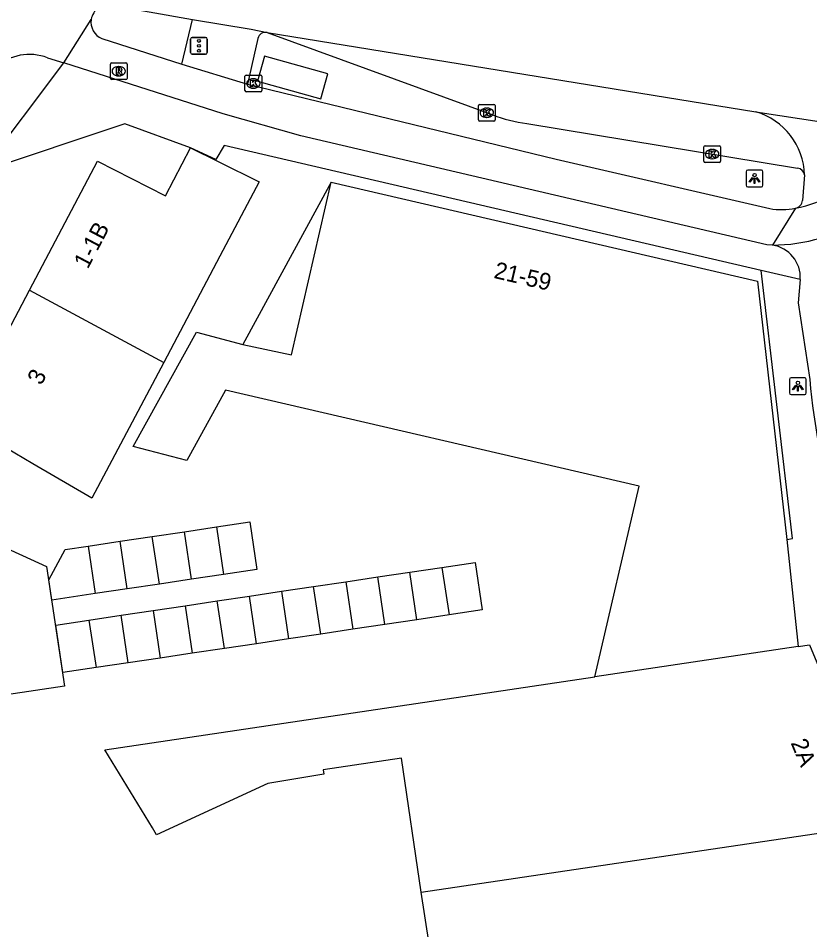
# Model space of a CAD drawing. Extents: x 161771 to 163125, y 382479 to 383177.
# Drawn here: x 161847.7 to 161894.8, y 383087.1 to 383141.3 of the extents above; entities that cross this region are included whole.
import ezdxf

# ---------------------------------------------------------------- set-up
doc = ezdxf.new("R2010")
doc.units = 0
for name, color, linetype in [('IMGEO_Fietspad_gesloten', 7, 'Continuous'), ('IMGEO_Kolk', 7, 'Continuous'), ('IMGEO_Lichtpunt', 7, 'Continuous'), ('IMGEO_Pand', 7, 'Continuous'), ('IMGEO_Pand_nummerreeks', 7, 'Continuous'), ('IMGEO_Pand_overbouw', 7, 'Continuous'), ('IMGEO_Rijbaan_lokaal_gesloten', 7, 'Continuous'), ('IMGEO_Rijbaan_lokaal_open', 7, 'Continuous'), ('IMGEO_Rioolput', 7, 'Continuous'), ('IMGEO_Verkeersregelinstallatiepaal', 7, 'Continuous'), ('IMGEO_Voetpad_gesloten', 7, 'Continuous'), ('IMGEO_Voetpad_open', 7, 'Continuous')]:
    doc.layers.add(name, color=color, linetype=linetype)

msp = doc.modelspace()

# ---------------------------------------------------------------- linework, layer by layer
at = {"layer": 'IMGEO_Fietspad_gesloten'}
for points in [[(161852.692, 383140.086), (161857.449, 383138.559)], [(161892.571, 383127.801), (161892.245, 383127.819), (161864.526, 383134.302), (161859.902, 383135.61), (161850.423, 383138.63)], [(161857.449, 383138.559), (161861.339, 383137.377)], [(161861.339, 383137.377), (161879.714, 383132.903), (161892.418, 383129.967)]]:
    msp.add_lwpolyline(points, dxfattribs=at)
for centre, radius, start, end in [((161853.077, 383141.052), 1.04, 170.4087, 248.2543), ((161893.117, 383134.045), 4.137, 260.2727, 281.4599)]:
    msp.add_arc(centre, radius, start, end, dxfattribs=at)
at = {"layer": 'IMGEO_Kolk'}
for p, q in [((161861.198, 383136.985), (161861.198, 383137.837)), ((161861.273, 383137.911), (161862.125, 383137.911)), ((161861.686, 383137.691), (161861.711, 383137.691)), ((161862.199, 383137.837), (161862.199, 383136.985)), ((161862.125, 383136.911), (161861.273, 383136.911)), ((161861.709, 383137.131), (161861.684, 383137.131)), ((161875.083, 383135.244), (161875.083, 383136.096)), ((161875.158, 383136.17), (161876.01, 383136.17)), ((161875.571, 383135.95), (161875.596, 383135.95)), ((161876.084, 383136.096), (161876.084, 383135.244)), ((161875.594, 383135.39), (161875.569, 383135.39)), ((161876.01, 383135.17), (161875.158, 383135.17)), ((161888.49, 383132.785), (161888.49, 383133.637)), ((161888.565, 383133.711), (161889.417, 383133.711)), ((161889.491, 383133.637), (161889.491, 383132.785)), ((161888.978, 383133.491), (161889.003, 383133.491)), ((161889.417, 383132.711), (161888.565, 383132.711)), ((161889.001, 383132.931), (161888.976, 383132.931))]:
    msp.add_line(p, q, dxfattribs=at)
for points in [[(161861.198, 383136.985), (161861.198, 383137.837)], [(161861.273, 383137.911), (161862.125, 383137.911)], [(161861.519, 383137.611), (161861.642, 383137.611), (161861.642, 383137.46), (161861.772, 383137.611), (161861.936, 383137.611), (161861.79, 383137.46), (161861.943, 383137.211), (161861.791, 383137.211), (161861.706, 383137.375), (161861.642, 383137.308), (161861.642, 383137.211), (161861.519, 383137.211), (161861.519, 383137.611)], [(161862.199, 383137.837), (161862.199, 383136.985)], [(161862.125, 383136.911), (161861.273, 383136.911)], [(161875.083, 383135.244), (161875.083, 383136.096)], [(161875.158, 383136.17), (161876.01, 383136.17)], [(161875.404, 383135.87), (161875.527, 383135.87), (161875.527, 383135.719), (161875.657, 383135.87), (161875.821, 383135.87), (161875.675, 383135.719), (161875.828, 383135.47), (161875.676, 383135.47), (161875.591, 383135.634), (161875.527, 383135.567), (161875.527, 383135.47), (161875.404, 383135.47), (161875.404, 383135.87)], [(161876.084, 383136.096), (161876.084, 383135.244)], [(161876.01, 383135.17), (161875.158, 383135.17)], [(161888.49, 383132.785), (161888.49, 383133.637)], [(161888.565, 383133.711), (161889.417, 383133.711)], [(161889.491, 383133.637), (161889.491, 383132.785)], [(161888.811, 383133.411), (161888.934, 383133.411), (161888.934, 383133.26), (161889.064, 383133.411), (161889.228, 383133.411), (161889.082, 383133.26), (161889.235, 383133.011), (161889.083, 383133.011), (161888.998, 383133.175), (161888.934, 383133.108), (161888.934, 383133.011), (161888.811, 383133.011), (161888.811, 383133.411)], [(161889.417, 383132.711), (161888.565, 383132.711)]]:
    msp.add_lwpolyline(points, dxfattribs=at)
for centre, start, end in [((161861.275, 383137.835), 91.552, 178.448), ((161861.275, 383137.835), 91.552, 178.448), ((161862.123, 383137.835), 1.552, 88.448), ((161862.123, 383137.835), 1.552, 88.448), ((161861.275, 383136.987), 181.552, 268.448), ((161861.275, 383136.987), 181.552, 268.448), ((161862.123, 383136.987), 271.552, 358.448), ((161862.123, 383136.987), 271.552, 358.448), ((161875.16, 383136.094), 91.552, 178.448), ((161875.16, 383136.094), 91.552, 178.448), ((161876.008, 383136.094), 1.552, 88.448), ((161876.008, 383136.094), 1.552, 88.448), ((161875.16, 383135.246), 181.552, 268.448), ((161875.16, 383135.246), 181.552, 268.448), ((161876.008, 383135.246), 271.552, 358.448), ((161876.008, 383135.246), 271.552, 358.448), ((161888.567, 383133.635), 91.552, 178.448), ((161888.567, 383133.635), 91.552, 178.448), ((161889.415, 383133.635), 1.552, 88.448), ((161889.415, 383133.635), 1.552, 88.448), ((161888.567, 383132.787), 181.552, 268.448), ((161888.567, 383132.787), 181.552, 268.448), ((161889.415, 383132.787), 271.552, 358.448), ((161889.415, 383132.787), 271.552, 358.448)]:
    msp.add_arc(centre, 0.0765, start, end, dxfattribs=at)
for centre, major_axis, ratio, start_param, end_param in [((161861.685, 383137.411), (-0.387, 0.002), 0.722429, 4.712389, 7.853982), ((161861.71, 383137.411), (-0.39, 0.002), 0.717154, 1.570796, 4.712389), ((161875.57, 383135.67), (-0.387, 0.002), 0.722429, 4.712389, 7.853982), ((161875.595, 383135.67), (-0.39, 0.002), 0.717154, 1.570796, 4.712389), ((161888.977, 383133.211), (-0.387, 0.002), 0.722429, 4.712389, 7.853982), ((161889.002, 383133.211), (-0.39, 0.002), 0.717154, 1.570796, 4.712389)]:
    msp.add_ellipse(centre, major_axis=major_axis, ratio=ratio, start_param=start_param, end_param=end_param, dxfattribs=at)
at = {"layer": 'IMGEO_Lichtpunt'}
for p, q in [((161891.013, 383132.163), (161891.013, 383131.356)), ((161891.013, 383132.163), (161891.013, 383131.356)), ((161891.915, 383132.258), (161891.107, 383132.258)), ((161891.915, 383132.258), (161891.107, 383132.258)), ((161892.009, 383131.356), (161892.009, 383132.163)), ((161892.009, 383131.356), (161892.009, 383132.163)), ((161891.107, 383131.262), (161891.915, 383131.262)), ((161891.107, 383131.262), (161891.915, 383131.262)), ((161893.591, 383119.812), (161893.591, 383119.005)), ((161893.591, 383119.812), (161893.591, 383119.005)), ((161894.493, 383119.907), (161893.685, 383119.907)), ((161894.493, 383119.907), (161893.685, 383119.907)), ((161894.587, 383119.005), (161894.587, 383119.812)), ((161894.587, 383119.005), (161894.587, 383119.812)), ((161893.685, 383118.911), (161894.493, 383118.911)), ((161893.685, 383118.911), (161894.493, 383118.911))]:
    msp.add_line(p, q, dxfattribs=at)
for points in [[(161891.387, 383131.827), (161891.426, 383131.799), (161891.238, 383131.537), (161891.2, 383131.564), (161891.387, 383131.827)], [(161891.489, 383131.779), (161891.536, 383131.779), (161891.536, 383131.457), (161891.489, 383131.457), (161891.489, 383131.779)], [(161891.599, 383131.799), (161891.637, 383131.826), (161891.824, 383131.564), (161891.785, 383131.536), (161891.599, 383131.799)], [(161893.965, 383119.476), (161894.004, 383119.448), (161893.816, 383119.186), (161893.778, 383119.213), (161893.965, 383119.476)], [(161894.067, 383119.428), (161894.114, 383119.428), (161894.114, 383119.106), (161894.067, 383119.106), (161894.067, 383119.428)], [(161894.177, 383119.448), (161894.215, 383119.475), (161894.402, 383119.213), (161894.363, 383119.185), (161894.177, 383119.448)]]:
    msp.add_lwpolyline(points, dxfattribs=at)
for centre in [(161891.512, 383131.961), (161894.09, 383119.61)]:
    msp.add_circle(centre, 0.0994, dxfattribs=at)
for centre, start, end in [((161891.107, 383132.163), 90, 180), ((161891.107, 383132.163), 90, 180), ((161891.915, 383132.163), 0, 90), ((161891.915, 383132.163), 0, 90), ((161891.107, 383131.356), 180, 270), ((161891.107, 383131.356), 180, 270), ((161891.915, 383131.356), 270, 0), ((161891.915, 383131.356), 270, 360), ((161893.685, 383119.812), 90, 180), ((161893.685, 383119.812), 90, 180), ((161894.493, 383119.812), 0, 90), ((161894.493, 383119.812), 0, 90), ((161893.685, 383119.005), 180, 270), ((161893.685, 383119.005), 180, 270), ((161894.493, 383119.005), 270, 0), ((161894.493, 383119.005), 270, 360)]:
    msp.add_arc(centre, 0.0946, start, end, dxfattribs=at)
at = {"layer": 'IMGEO_Pand'}
for points in [[(161848.381, 383125.126), (161852.425, 383132.793), (161856.463, 383130.733), (161857.966, 383133.582)], [(161857.966, 383133.582), (161859.652, 383132.746), (161862.05, 383131.558), (161859.711, 383127.14), (161856.369, 383120.828)], [(161882.018, 383102.128), (161884.644, 383113.47), (161860.047, 383119.164), (161857.73, 383114.985), (161854.545, 383115.819), (161858.313, 383122.616), (161861.079, 383121.891), (161863.959, 383121.281), (161866.335, 383131.551), (161891.687, 383125.659), (161893.432, 383110.294)], [(161856.369, 383120.828), (161852.087, 383112.742), (161848.581, 383114.799), (161844.268, 383117.328), (161848.381, 383125.126)], [(161848.381, 383125.126), (161856.369, 383120.828)], [(161857.594, 383110.758), (161859.503, 383111.043)], [(161859.503, 383111.043), (161861.481, 383111.338), (161861.903, 383108.509), (161859.925, 383108.214)], [(161859.503, 383111.043), (161859.925, 383108.214)], [(161853.776, 383110.188), (161855.685, 383110.473)], [(161855.685, 383110.473), (161857.594, 383110.758)], [(161856.107, 383107.644), (161855.685, 383110.473)], [(161858.016, 383107.929), (161857.594, 383110.758)], [(161846.3, 383110.089), (161849.393, 383108.697), (161850.457, 383101.576), (161843.141, 383100.485)], [(161852.289, 383107.074), (161849.718, 383106.69), (161849.539, 383107.887), (161850.502, 383109.699), (161851.867, 383109.903)], [(161851.867, 383109.903), (161853.776, 383110.188)], [(161851.867, 383109.903), (161852.289, 383107.074)], [(161854.198, 383107.359), (161853.776, 383110.188)], [(161893.432, 383110.294), (161894.113, 383103.934)], [(161872.915, 383108.636), (161874.893, 383108.931), (161875.315, 383106.102), (161873.337, 383105.807)], [(161859.925, 383108.214), (161858.016, 383107.929)], [(161869.097, 383108.066), (161871.006, 383108.351)], [(161871.006, 383108.351), (161872.915, 383108.636)], [(161871.428, 383105.522), (161871.006, 383108.351)], [(161872.915, 383108.636), (161873.337, 383105.807)], [(161856.107, 383107.644), (161854.198, 383107.359)], [(161858.016, 383107.929), (161856.107, 383107.644)], [(161865.279, 383107.496), (161867.188, 383107.781)], [(161867.188, 383107.781), (161869.097, 383108.066)], [(161867.188, 383107.781), (161867.61, 383104.952)], [(161869.519, 383105.237), (161869.097, 383108.066)], [(161854.198, 383107.359), (161852.289, 383107.074)], [(161861.462, 383106.927), (161863.371, 383107.211)], [(161863.371, 383107.211), (161865.279, 383107.496)], [(161863.371, 383107.211), (161863.793, 383104.382)], [(161865.702, 383104.667), (161865.279, 383107.496)], [(161857.644, 383106.357), (161859.553, 383106.642)], [(161859.553, 383106.642), (161861.462, 383106.927)], [(161859.975, 383103.813), (161859.553, 383106.642)], [(161861.884, 383104.098), (161861.462, 383106.927)], [(161853.826, 383105.787), (161855.735, 383106.072)], [(161855.735, 383106.072), (161857.644, 383106.357)], [(161855.735, 383106.072), (161856.157, 383103.243)], [(161857.644, 383106.357), (161858.066, 383103.528)], [(161852.34, 383102.673), (161850.361, 383102.378), (161849.939, 383105.207), (161851.917, 383105.502)], [(161851.917, 383105.502), (161853.826, 383105.787)], [(161851.917, 383105.502), (161852.34, 383102.673)], [(161854.248, 383102.958), (161853.826, 383105.787)], [(161871.428, 383105.522), (161869.519, 383105.237)], [(161873.337, 383105.807), (161871.428, 383105.522)], [(161867.61, 383104.952), (161865.702, 383104.667)], [(161869.519, 383105.237), (161867.61, 383104.952)], [(161863.793, 383104.382), (161861.884, 383104.098)], [(161865.702, 383104.667), (161863.793, 383104.382)], [(161859.975, 383103.813), (161858.066, 383103.528)], [(161861.884, 383104.098), (161859.975, 383103.813)], [(161894.113, 383103.934), (161882.018, 383102.128)], [(161894.113, 383103.934), (161894.772, 383104.032), (161899.195, 383093.413)], [(161858.066, 383103.528), (161856.157, 383103.243)], [(161854.248, 383102.958), (161852.34, 383102.673)], [(161856.157, 383103.243), (161854.248, 383102.958)], [(161871.689, 383089.325), (161870.502, 383097.282), (161865.845, 383096.588), (161865.887, 383096.331), (161862.556, 383095.791), (161855.928, 383092.724), (161855.697, 383093.142), (161852.864, 383097.777), (161882.018, 383102.128)], [(161871.689, 383089.325), (161899.195, 383093.413)], [(161881.294, 383072.642), (161872.184, 383086.008), (161872.148, 383086.252), (161871.689, 383089.325)]]:
    msp.add_lwpolyline(points, dxfattribs=at)
at = {"layer": 'IMGEO_Pand_overbouw'}
msp.add_lwpolyline([(161861.079, 383121.891), (161863.959, 383121.281), (161866.335, 383131.551)], close=True, dxfattribs=at)
at = {"layer": 'IMGEO_Rijbaan_lokaal_gesloten'}
for points in [[(161853.259, 383142.074), (161858.074, 383141.224)], [(161850.423, 383138.63), (161852.052, 383141.225)], [(161858.074, 383141.224), (161861.557, 383140.632), (161862.515, 383140.445)], [(161862.515, 383140.445), (161891.594, 383135.723)], [(161849.452, 383138.944), (161850.423, 383138.63)], [(161891.594, 383135.723), (161906.528, 383133.437)], [(161894.49, 383131.976), (161894.362, 383130.459)], [(161893.939, 383129.99), (161892.571, 383127.801)]]:
    msp.add_lwpolyline(points, dxfattribs=at)
for centre, radius, start, end in [((161853.078, 383141.048), 1.042, 80.015, 170.2298), ((161848.382, 383136.084), 3.054, 69.4984, 131.7476), ((161890.469, 383131.861), 4.023, 1.6449, 73.7549), ((161892.305, 383138.212), 8.382, 281.2401, 298.5711), ((161893.833, 383130.51), 0.531, 281.463, 354.4412), ((161892.497, 383138.36), 10.56, 270.4019, 301.9765)]:
    msp.add_arc(centre, radius, start, end, dxfattribs=at)
at = {"layer": 'IMGEO_Rijbaan_lokaal_open'}
for points in [[(161862.515, 383140.445), (161875.938, 383135.541)], [(161877.967, 383135.025), (161894.071, 383132.375)], [(161894.232, 383125.758), (161894.106, 383124.369), (161894.796, 383119.807)]]:
    msp.add_lwpolyline(points, dxfattribs=at)
for centre, radius, start, end in [((161879.058, 383143.561), 8.605, 248.7442, 262.7187), ((161894.016, 383131.898), 0.48, 9.3586, 83.4426), ((161892.275, 383125.864), 1.96, 356.9024, 81.3212), ((161945.388, 383124.557), 50.815, 185.3632, 194.8819)]:
    msp.add_arc(centre, radius, start, end, dxfattribs=at)
at = {"layer": 'IMGEO_Rioolput'}
for p, q in [((161853.189, 383137.713), (161853.189, 383138.565)), ((161853.264, 383138.639), (161854.116, 383138.639)), ((161854.19, 383138.565), (161854.19, 383137.713)), ((161853.677, 383138.419), (161853.702, 383138.419)), ((161854.116, 383137.639), (161853.264, 383137.639)), ((161853.7, 383137.859), (161853.675, 383137.859))]:
    msp.add_line(p, q, dxfattribs=at)
for points in [[(161853.189, 383137.713), (161853.189, 383138.565)], [(161853.264, 383138.639), (161854.116, 383138.639)], [(161854.19, 383138.565), (161854.19, 383137.713)], [(161853.778, 383138.337), (161853.526, 383138.339), (161853.526, 383137.939)], [(161853.526, 383137.939), (161853.65, 383137.939), (161853.65, 383138.101), (161853.661, 383138.101)], [(161853.704, 383138.258), (161853.65, 383138.258), (161853.65, 383138.177)], [(161853.65, 383138.177), (161853.702, 383138.177)], [(161853.708, 383138.072), (161853.779, 383137.939), (161853.919, 383137.939), (161853.854, 383138.065)], [(161854.116, 383137.639), (161853.264, 383137.639)]]:
    msp.add_lwpolyline(points, dxfattribs=at)
for centre, radius, start, end in [((161853.266, 383138.563), 0.0765, 91.552, 178.448), ((161853.266, 383138.563), 0.0765, 91.552, 178.448), ((161854.114, 383138.563), 0.0765, 1.552, 88.448), ((161854.114, 383138.563), 0.0765, 1.552, 88.448), ((161853.66, 383138.048), 0.0533, 26.0293, 88.6989), ((161853.686, 383138.366), 0.19, 274.7715, 282.9687), ((161853.71, 383138.162), 0.0964, 77.0061, 93.1865), ((161853.724, 383138.219), 0.0378, 276.6634, 79.6772), ((161853.777, 383138.227), 0.109, 350.3612, 89.416), ((161853.775, 383138.227), 0.112, 277.5842, 350.9817), ((161853.759, 383138.012), 0.108, 29.5134, 73.7905), ((161853.266, 383137.715), 0.0765, 181.552, 268.448), ((161853.266, 383137.715), 0.0765, 181.552, 268.448), ((161854.114, 383137.715), 0.0765, 271.552, 358.448), ((161854.114, 383137.715), 0.0765, 271.552, 358.448)]:
    msp.add_arc(centre, radius, start, end, dxfattribs=at)
for centre, major_axis, ratio, start_param, end_param in [((161853.676, 383138.139), (-0.387, 0.002), 0.722429, 4.712389, 7.853982), ((161853.701, 383138.139), (-0.39, 0.002), 0.717154, 1.570796, 4.712389)]:
    msp.add_ellipse(centre, major_axis=major_axis, ratio=ratio, start_param=start_param, end_param=end_param, dxfattribs=at)
at = {"layer": 'IMGEO_Verkeersregelinstallatiepaal'}
for p, q in [((161858.063, 383140.148), (161858.853, 383140.148)), ((161858.853, 383140.148), (161858.063, 383140.148)), ((161857.963, 383139.248), (161857.963, 383140.048)), ((161857.963, 383140.048), (161857.963, 383139.248)), ((161858.953, 383140.048), (161858.953, 383139.248)), ((161858.953, 383139.248), (161858.953, 383140.048)), ((161858.853, 383139.148), (161858.063, 383139.148)), ((161858.063, 383139.148), (161858.853, 383139.148))]:
    msp.add_line(p, q, dxfattribs=at)
for centre in [(161858.458, 383139.938), (161858.458, 383139.648), (161858.458, 383139.358)]:
    msp.add_circle(centre, 0.085, dxfattribs=at)
for centre, start, end in [((161858.063, 383140.048), 90, 180), ((161858.063, 383140.048), 90, 180), ((161858.853, 383140.048), 0, 90), ((161858.853, 383140.048), 360, 90), ((161858.063, 383139.248), 180, 270), ((161858.063, 383139.248), 180, 270), ((161858.853, 383139.248), 270, 0), ((161858.853, 383139.248), 270, 0)]:
    msp.add_arc(centre, 0.1, start, end, dxfattribs=at)
at = {"layer": 'IMGEO_Voetpad_gesloten'}
msp.add_lwpolyline([(161866.132, 383137.984), (161862.352, 383139.044), (161861.935, 383137.557), (161865.715, 383136.497), (161866.132, 383137.984)], dxfattribs=at)
at = {"layer": 'IMGEO_Voetpad_open'}
for points in [[(161857.449, 383138.559), (161858.074, 383141.224)], [(161861.96, 383140.092), (161861.339, 383137.377)], [(161845.553, 383132.186), (161850.423, 383138.63)], [(161857.966, 383133.582), (161854.053, 383135.016), (161845.553, 383132.186)], [(161891.895, 383126.294), (161859.967, 383133.719), (161859.465, 383132.882), (161857.966, 383133.582)], [(161893.432, 383110.294), (161893.776, 383110.359), (161891.895, 383126.294)], [(161894.232, 383125.758), (161891.895, 383126.294)]]:
    msp.add_lwpolyline(points, dxfattribs=at)
msp.add_arc((161862.436, 383139.957), 0.494, 80.7611, 164.1545, dxfattribs=at)

# ---------------------------------------------------------------- texts
at = {"layer": 'IMGEO_Pand_nummerreeks'}
for s, rotation, p in [('1-1B', 62.1888, (161851.846, 383126.336)), ('21-59', 346.8656, (161875.953, 383125.855)), ('3', 62.1906, (161849.08, 383119.42)), ('2A', 292.6144, (161893.646, 383098.204))]:
    msp.add_text(s, height=1, rotation=rotation, dxfattribs=at).set_placement(p)

doc.saveas('drawing.dxf')
